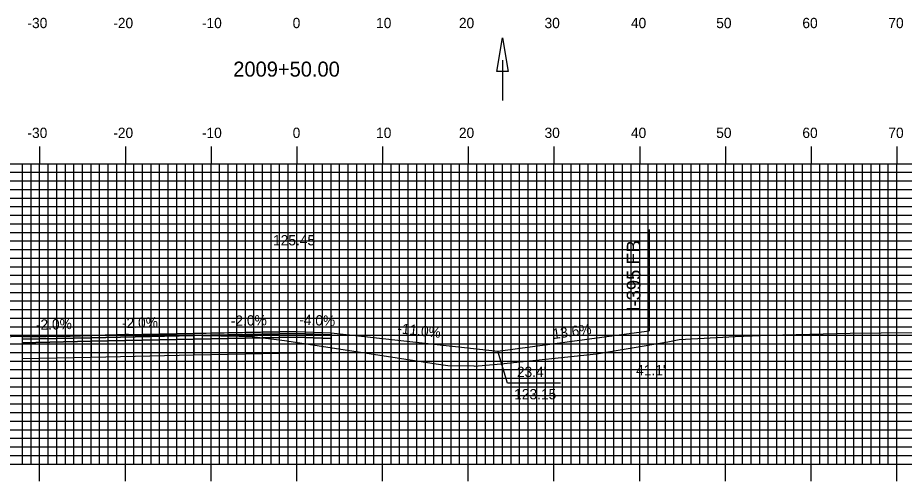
# Model space of a CAD drawing. Extents: x 853107 to 853450, y 366605 to 366825.
# Drawn here: x 853239.9 to 853343.4, y 366681.1 to 366735.1 of the extents above; entities that cross this region are included whole.
import ezdxf

# ---------------------------------------------------------------- set-up
doc = ezdxf.new("R2010")
doc.units = 0
for name, color, linetype in [('ANNOTATION', 7, 'Continuous'), ('D_Drainage_Ditch_Line', 7, 'Continuous'), ('D_Drainage_Underdrain', 7, 'Continuous'), ('D_Roadway_Centerline', 7, 'Continuous'), ('D_Roadway_Centerline_Text', 7, 'Continuous'), ('D_Roadway_Edge_Shoulder', 7, 'Continuous'), ('D_Roadway_Edge_TW', 7, 'Continuous'), ('D_Roadway_Pavement', 7, 'Continuous'), ('D_Roadway_SubGrade', 7, 'Continuous'), ('D_Text_Standard', 7, 'Continuous'), ('H_V ANNOTATION', 7, 'Continuous'), ('M_Roadway_Centerline', 7, 'Continuous'), ('MAJOR', 7, 'Continuous'), ('MINOR', 7, 'Continuous'), ('S_Roadway_Centerline', 7, 'Continuous')]:
    doc.layers.add(name, color=color, linetype=linetype)

msp = doc.modelspace()

# ---------------------------------------------------------------- linework, layer by layer
at = {"layer": 'ANNOTATION'}
msp.add_lwpolyline([(853303.26, 366692.47), (853297.09, 366692.47), (853295.94, 366696.2)], dxfattribs=at)
at = {"layer": 'D_Drainage_Ditch_Line'}
msp.add_line((853296.5, 366730.12), (853296.5, 366725.42), dxfattribs=at)
msp.add_lwpolyline([(853297.15, 366728.81), (853295.84, 366728.81), (853296.5, 366732.75)], close=True, dxfattribs=at)
at = {"layer": 'D_Drainage_Underdrain'}
msp.add_lwpolyline([(853240.45, 366697.87), (853240.45, 366695.37), (853248.5, 366695.53)], dxfattribs=at)
at = {"layer": 'D_Roadway_Centerline'}
for points in [[(853240.45, 366697.87), (853240.46, 366697.87), (853246.08, 366697.98), (853248.5, 366698.03), (853248.5, 366698.03), (853248.51, 366698.03), (853260.5, 366698.27), (853261.92, 366698.3), (853272.5, 366698.51), (853273.45, 366698.47), (853276.5, 366698.35), (853284.98, 366697.41), (853295.94, 366696.2)], [(853276.5, 366698.35), (853295.94, 366696.2)], [(853295.94, 366696.2), (853312.13, 366698.4), (853313.61, 366698.6)]]:
    msp.add_lwpolyline(points, dxfattribs=at)
at = {"layer": 'D_Roadway_Edge_Shoulder'}
msp.add_lwpolyline([(853272.5, 366698.51), (853276.5, 366698.35), (853276.5, 366698.1), (853272.5, 366698.26)], close=True, dxfattribs=at)
at = {"layer": 'D_Roadway_Edge_TW'}
for points in [[(853248.5, 366698.03), (853240.45, 366697.87), (853240.45, 366697.62), (853248.5, 366697.78)], [(853260.5, 366698.27), (853248.5, 366698.03), (853248.5, 366697.78), (853260.5, 366698.02)], [(853272.5, 366698.51), (853260.5, 366698.27), (853260.5, 366698.02), (853272.5, 366698.26)]]:
    msp.add_lwpolyline(points, close=True, dxfattribs=at)
at = {"layer": 'D_Roadway_Pavement'}
for points in [[(853260.5, 366698.02), (853248.5, 366697.78), (853248.5, 366697.36), (853260.5, 366697.6)], [(853272.5, 366698.26), (853260.5, 366698.02), (853260.5, 366697.6), (853272.5, 366697.84)], [(853272.5, 366698.26), (853276.5, 366698.1), (853276.5, 366697.68), (853272.5, 366697.84)], [(853248.5, 366697.78), (853240.45, 366697.62), (853240.45, 366697.2), (853248.5, 366697.36)]]:
    msp.add_lwpolyline(points, close=True, dxfattribs=at)
msp.add_lwpolyline([(853260.5, 366698.02), (853260.5, 366697.6)], dxfattribs=at)
at = {"layer": 'D_Roadway_SubGrade'}
for p, q in [((853313.61, 366710.41), (853313.61, 366698.6)), ((853240.45, 366709.68), (853240.45, 366695.37))]:
    msp.add_line(p, q, dxfattribs=at)
for points in [[(853272.5, 366697.84), (853276.5, 366697.68), (853276.5, 366698.1), (853276.5, 366698.35), (853276.5, 366695.93), (853272.5, 366696.01)], [(853248.5, 366697.36), (853240.45, 366697.2), (853240.45, 366697.2), (853240.45, 366695.37), (853248.5, 366695.53)], [(853260.5, 366697.6), (853248.5, 366697.36), (853248.5, 366695.53), (853260.5, 366695.77)], [(853272.5, 366697.84), (853260.5, 366697.6), (853260.5, 366695.77), (853272.5, 366696.01)]]:
    msp.add_lwpolyline(points, close=True, dxfattribs=at)
at = {"layer": 'MAJOR'}
for p, q in [((853242.5, 366720.06), (853242.5, 366718.06)), ((853252.5, 366720.06), (853252.5, 366718.06)), ((853262.5, 366720.06), (853262.5, 366718.06)), ((853272.5, 366720.06), (853272.5, 366718.06)), ((853282.5, 366720.06), (853282.5, 366718.06)), ((853292.5, 366720.06), (853292.5, 366718.06)), ((853302.5, 366720.06), (853302.5, 366718.06)), ((853312.5, 366720.06), (853312.5, 366718.06)), ((853322.5, 366720.06), (853322.5, 366718.06)), ((853332.5, 366720.06), (853332.5, 366718.06)), ((853342.5, 366720.06), (853342.5, 366718.06)), ((853132.5, 366718.06), (853412.5, 366718.06)), ((853132.5, 366718.06), (853412.5, 366718.06)), ((853242.5, 366683.06), (853242.5, 366718.06)), ((853252.5, 366683.06), (853252.5, 366718.06)), ((853262.5, 366683.06), (853262.5, 366718.06)), ((853272.5, 366683.06), (853272.5, 366718.06)), ((853282.5, 366683.06), (853282.5, 366718.06)), ((853292.5, 366683.06), (853292.5, 366718.06)), ((853302.5, 366683.06), (853302.5, 366718.06)), ((853312.5, 366683.06), (853312.5, 366718.06)), ((853322.5, 366683.06), (853322.5, 366718.06)), ((853332.5, 366683.06), (853332.5, 366718.06)), ((853342.5, 366683.06), (853342.5, 366718.06)), ((853132.5, 366713.06), (853412.5, 366713.06)), ((853132.5, 366708.06), (853412.5, 366708.06)), ((853132.5, 366703.06), (853412.5, 366703.06)), ((853132.5, 366698.06), (853412.5, 366698.06)), ((853132.5, 366693.06), (853412.5, 366693.06)), ((853132.5, 366688.06), (853412.5, 366688.06)), ((853132.5, 366683.06), (853412.5, 366683.06)), ((853132.5, 366683.06), (853412.5, 366683.06)), ((853242.5, 366681.05), (853242.5, 366683.06)), ((853252.5, 366681.05), (853252.5, 366683.06)), ((853262.5, 366681.05), (853262.5, 366683.06)), ((853272.5, 366681.05), (853272.5, 366683.06)), ((853282.5, 366681.05), (853282.5, 366683.06)), ((853292.5, 366681.05), (853292.5, 366683.06)), ((853302.5, 366681.05), (853302.5, 366683.06)), ((853312.5, 366681.05), (853312.5, 366683.06)), ((853322.5, 366681.05), (853322.5, 366683.06)), ((853332.5, 366681.05), (853332.5, 366683.06)), ((853342.5, 366681.05), (853342.5, 366683.06))]:
    msp.add_line(p, q, dxfattribs=at)
at = {"layer": 'MINOR'}
for p, q in [((853240.5, 366683.06), (853240.5, 366718.06)), ((853241.5, 366683.06), (853241.5, 366718.06)), ((853243.5, 366683.06), (853243.5, 366718.06)), ((853244.5, 366683.06), (853244.5, 366718.06)), ((853245.5, 366683.06), (853245.5, 366718.06)), ((853246.5, 366683.06), (853246.5, 366718.06)), ((853247.5, 366683.06), (853247.5, 366718.06)), ((853248.5, 366683.06), (853248.5, 366718.06)), ((853249.5, 366683.06), (853249.5, 366718.06)), ((853250.5, 366683.06), (853250.5, 366718.06)), ((853251.5, 366683.06), (853251.5, 366718.06)), ((853253.5, 366683.06), (853253.5, 366718.06)), ((853254.5, 366683.06), (853254.5, 366718.06)), ((853255.5, 366683.06), (853255.5, 366718.06)), ((853256.5, 366683.06), (853256.5, 366718.06)), ((853257.5, 366683.06), (853257.5, 366718.06)), ((853258.5, 366683.06), (853258.5, 366718.06)), ((853259.5, 366683.06), (853259.5, 366718.06)), ((853260.5, 366683.06), (853260.5, 366718.06)), ((853261.5, 366683.06), (853261.5, 366718.06)), ((853263.5, 366683.06), (853263.5, 366718.06)), ((853264.5, 366683.06), (853264.5, 366718.06)), ((853265.5, 366683.06), (853265.5, 366718.06)), ((853266.5, 366683.06), (853266.5, 366718.06)), ((853267.5, 366683.06), (853267.5, 366718.06)), ((853268.5, 366683.06), (853268.5, 366718.06)), ((853269.5, 366683.06), (853269.5, 366718.06)), ((853270.5, 366683.06), (853270.5, 366718.06)), ((853271.5, 366683.06), (853271.5, 366718.06)), ((853273.5, 366683.06), (853273.5, 366718.06)), ((853274.5, 366683.06), (853274.5, 366718.06)), ((853275.5, 366683.06), (853275.5, 366718.06)), ((853276.5, 366683.06), (853276.5, 366718.06)), ((853277.5, 366683.06), (853277.5, 366718.06)), ((853278.5, 366683.06), (853278.5, 366718.06)), ((853279.5, 366683.06), (853279.5, 366718.06)), ((853280.5, 366683.06), (853280.5, 366718.06)), ((853281.5, 366683.06), (853281.5, 366718.06)), ((853283.5, 366683.06), (853283.5, 366718.06)), ((853284.5, 366683.06), (853284.5, 366718.06)), ((853285.5, 366683.06), (853285.5, 366718.06)), ((853286.5, 366683.06), (853286.5, 366718.06)), ((853287.5, 366683.06), (853287.5, 366718.06)), ((853288.5, 366683.06), (853288.5, 366718.06)), ((853289.5, 366683.06), (853289.5, 366718.06)), ((853290.5, 366683.06), (853290.5, 366718.06)), ((853291.5, 366683.06), (853291.5, 366718.06)), ((853293.5, 366683.06), (853293.5, 366718.06)), ((853294.5, 366683.06), (853294.5, 366718.06)), ((853295.5, 366683.06), (853295.5, 366718.06)), ((853296.5, 366683.06), (853296.5, 366718.06)), ((853297.5, 366683.06), (853297.5, 366718.06)), ((853298.5, 366683.06), (853298.5, 366718.06)), ((853299.5, 366683.06), (853299.5, 366718.06)), ((853300.5, 366683.06), (853300.5, 366718.06)), ((853301.5, 366683.06), (853301.5, 366718.06)), ((853303.5, 366683.06), (853303.5, 366718.06)), ((853304.5, 366683.06), (853304.5, 366718.06)), ((853305.5, 366683.06), (853305.5, 366718.06)), ((853306.5, 366683.06), (853306.5, 366718.06)), ((853307.5, 366683.06), (853307.5, 366718.06)), ((853308.5, 366683.06), (853308.5, 366718.06)), ((853309.5, 366683.06), (853309.5, 366718.06)), ((853310.5, 366683.06), (853310.5, 366718.06)), ((853311.5, 366683.06), (853311.5, 366718.06)), ((853313.5, 366683.06), (853313.5, 366718.06)), ((853314.5, 366683.06), (853314.5, 366718.06)), ((853315.5, 366683.06), (853315.5, 366718.06)), ((853316.5, 366683.06), (853316.5, 366718.06)), ((853317.5, 366683.06), (853317.5, 366718.06)), ((853318.5, 366683.06), (853318.5, 366718.06)), ((853319.5, 366683.06), (853319.5, 366718.06)), ((853320.5, 366683.06), (853320.5, 366718.06)), ((853321.5, 366683.06), (853321.5, 366718.06)), ((853323.5, 366683.06), (853323.5, 366718.06)), ((853324.5, 366683.06), (853324.5, 366718.06)), ((853325.5, 366683.06), (853325.5, 366718.06)), ((853326.5, 366683.06), (853326.5, 366718.06)), ((853327.5, 366683.06), (853327.5, 366718.06)), ((853328.5, 366683.06), (853328.5, 366718.06)), ((853329.5, 366683.06), (853329.5, 366718.06)), ((853330.5, 366683.06), (853330.5, 366718.06)), ((853331.5, 366683.06), (853331.5, 366718.06)), ((853333.5, 366683.06), (853333.5, 366718.06)), ((853334.5, 366683.06), (853334.5, 366718.06)), ((853335.5, 366683.06), (853335.5, 366718.06)), ((853336.5, 366683.06), (853336.5, 366718.06)), ((853337.5, 366683.06), (853337.5, 366718.06)), ((853338.5, 366683.06), (853338.5, 366718.06)), ((853339.5, 366683.06), (853339.5, 366718.06)), ((853340.5, 366683.06), (853340.5, 366718.06)), ((853341.5, 366683.06), (853341.5, 366718.06)), ((853132.5, 366717.06), (853412.5, 366717.06)), ((853132.5, 366716.06), (853412.5, 366716.06)), ((853132.5, 366715.06), (853412.5, 366715.06)), ((853132.5, 366714.06), (853412.5, 366714.06)), ((853132.5, 366712.06), (853412.5, 366712.06)), ((853132.5, 366711.06), (853412.5, 366711.06)), ((853132.5, 366710.06), (853412.5, 366710.06)), ((853132.5, 366709.06), (853412.5, 366709.06)), ((853132.5, 366707.06), (853412.5, 366707.06)), ((853132.5, 366706.06), (853412.5, 366706.06)), ((853132.5, 366705.06), (853412.5, 366705.06)), ((853132.5, 366704.06), (853412.5, 366704.06)), ((853132.5, 366702.06), (853412.5, 366702.06)), ((853132.5, 366701.06), (853412.5, 366701.06)), ((853132.5, 366700.06), (853412.5, 366700.06)), ((853132.5, 366699.06), (853412.5, 366699.06)), ((853132.5, 366697.06), (853412.5, 366697.06)), ((853132.5, 366696.06), (853412.5, 366696.06)), ((853132.5, 366695.06), (853412.5, 366695.06)), ((853132.5, 366694.06), (853412.5, 366694.06)), ((853132.5, 366692.06), (853412.5, 366692.06)), ((853132.5, 366691.06), (853412.5, 366691.06)), ((853132.5, 366690.06), (853412.5, 366690.06)), ((853132.5, 366689.06), (853412.5, 366689.06)), ((853132.5, 366687.06), (853412.5, 366687.06)), ((853132.5, 366686.06), (853412.5, 366686.06)), ((853132.5, 366685.06), (853412.5, 366685.06)), ((853132.5, 366684.06), (853412.5, 366684.06))]:
    msp.add_line(p, q, dxfattribs=at)
at = {"layer": 'S_Roadway_Centerline'}
msp.add_lwpolyline([(853232.64, 366697.78), (853240.8, 366697.96), (853245, 366698.06), (853245.91, 366698.08), (853250.13, 366698.13), (853251.53, 366698.16), (853252.5, 366698.19), (853252.86, 366698.19), (853265.77, 366697.98), (853267.31, 366697.96), (853267.31, 366697.91), (853271.08, 366697.46), (853289.05, 366694.68), (853290.14, 366694.54), (853293.17, 366694.49), (853293.22, 366694.48), (853296.3, 366694.74), (853307.46, 366695.9), (853315.78, 366697.31), (853317.12, 366697.58), (853323.63, 366697.92), (853327.59, 366698.08), (853337.05, 366698.31), (853340.69, 366698.36), (853342.42, 366698.37), (853347.08, 366698.31)], dxfattribs=at)

# ---------------------------------------------------------------- texts
at = {"layer": 'ANNOTATION'}
for s, height, rotation, p in [('I-395 EB', 1.6, 90, (853312.59, 366700.83)), ('-2.0%', 1.2, 1.1458, (853242.08, 366698.7)), ('-2.0%', 1.2, 1.1458, (853252.12, 366698.9)), ('-2.0%', 1.2, 1.1458, (853264.82, 366699.15)), ('-4.0%', 1.2, 357.7093, (853272.77, 366699.3)), ('-11.0%', 1.2, 353.7062, (853284.18, 366698.31)), ('13.6%', 1.2, 7.7232, (853302.43, 366697.62)), ("23.4' ", 1.2, 360, (853298.18, 366693.2)), ('123.15', 1.2, 360, (853297.86, 366690.6))]:
    msp.add_text(s, height=height, rotation=rotation, dxfattribs=at).set_placement(p)
at = {"layer": 'D_Roadway_Centerline_Text'}
msp.add_text('125.45', height=1.2, dxfattribs=at).set_placement((853269.73, 366708.54))
at = {"layer": 'D_Text_Standard'}
msp.add_text("41.1'", height=1.2, dxfattribs=at).set_placement((853312.09, 366693.4))
at = {"layer": 'H_V ANNOTATION'}
for s, height, p in [('-30', 1.2, (853241.08, 366733.86)), ('-20', 1.2, (853251.09, 366733.86)), ('-10', 1.2, (853261.43, 366733.86)), ('0', 1.2, (853272.02, 366733.86)), ('10', 1.2, (853281.75, 366733.86)), ('20', 1.2, (853291.41, 366733.86)), ('30', 1.2, (853301.4, 366733.86)), ('40', 1.2, (853311.48, 366733.86)), ('50', 1.2, (853321.43, 366733.86)), ('60', 1.2, (853331.48, 366733.86)), ('70', 1.2, (853341.51, 366733.86)), ('2009+50.00', 1.75, (853265.09, 366728.21)), ('-30', 1.2, (853241.08, 366721.06)), ('-20', 1.2, (853251.09, 366721.06)), ('-10', 1.2, (853261.43, 366721.06)), ('0', 1.2, (853272.02, 366721.06)), ('10', 1.2, (853281.75, 366721.06)), ('20', 1.2, (853291.41, 366721.06)), ('30', 1.2, (853301.4, 366721.06)), ('40', 1.2, (853311.48, 366721.06)), ('50', 1.2, (853321.43, 366721.06)), ('60', 1.2, (853331.48, 366721.06)), ('70', 1.2, (853341.51, 366721.06))]:
    msp.add_text(s, height=height, dxfattribs=at).set_placement(p)
at = {"layer": 'M_Roadway_Centerline'}
for s, p in [('C', (853251.53, 366698.16)), ('L', (853251.53, 366698.15)), ('C', (853342.42, 366698.37)), ('L', (853342.42, 366698.36))]:
    msp.add_text(s, height=0.0146, dxfattribs=at).set_placement(p)

doc.saveas('drawing.dxf')
